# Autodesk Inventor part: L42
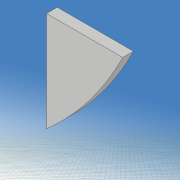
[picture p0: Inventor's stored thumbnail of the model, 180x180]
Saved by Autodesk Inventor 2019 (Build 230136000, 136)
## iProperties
Created: 2021-05
Part Number: L42
Material: 一般
Document SubType Name: Modeling
Designer: kikut
Density: 1 g/cm^3
Appearance: 既定
Mass: 0.00934248 g
Surface Area: 0.426451 cm^2
Volume: 0.00934248 cm^3
Author: kikut
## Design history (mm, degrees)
sketch "スケッチ1"
  geometry: L1 (80, 60)-(-80, 60); L2 (-80, 60)-(-80, -60); L3 (-80, -60)-(80, -60); L4 (80, -60)-(80, 60); L5 (80, 60)-(-80, -60); L6 (-80, 60)-(80, -60); 1 further point
  constraints: 12 end point, 2 midpoint, 2 parallel, 1 horizontal, 1 perpendicular
  dimensions: "d0" = 160 distance of L2.end L3.end; "d1" = 120 distance of L1.end L2.end
extrude "押し出し1" new body sketch "スケッチ1" stored distance "d2" = 0.6; taper "d3" = 0 deg
sketch "スケッチ2"
  geometry: L1 (-140, 0)-(140, 0) reference; L2 (0, -54)-(20, -30); L3 (0, 54)-(20, 30); L4 (0, -3)-(6.514, -3); L5 (6.514, -3)-(16, -6); L6 (16, -6)-(24, -3); L7 (24, -3)-(33.716, -3); L8 (0, 3)-(6.514, 3); L9 (6.514, 3)-(16, 6); L10 (16, 6)-(24, 3); L11 (24, 3)-(33.716, 3); L12 (0, -98)-(0, 98) reference; L13 (-100, -70)-(100, -70); L14 (100, -70)-(100, 70); L15 (100, 70)-(-100, 70); L16 (-100, 70)-(-100, -70); L17 (-100, -70)-(100, 70); L18 (100, -70)-(-100, 70); A1 r 60 centre (54.312, 28.5) between (0, 54) and (0, 3); A2 r 60 centre (54.312, -28.5) between (0, -3) and (0, -54); A3 r 18.111 centre (18, -12) between (20, -30) and (33.716, -3); A4 r 18.111 centre (18, 12) between (33.716, 3) and (20, 30); 1 further point
  constraints: 32 end point, 8 point on circle, 8 symmetric about line, 4 centre point, 3 horizontal, 2 collinear, 2 midpoint, 2 parallel, 1 perpendicular
  dimensions: "d5" = 60 radius of A1; "d6" = 6 distance of L8.start L4.start; "d7" = 108 distance of L3.start L2.start; "d8" = 0 horizontal distance of L3.start L8.start; "d9" = 60 distance of L3.end L2.end; "d10" = 0 horizontal distance of point (0, 0) L3.start; "d11" = 20 horizontal distance of L3.start L3.end; "d12" = 24 distance of A4.centre A3.centre; "d13" = 6 distance of L11.end L7.end; "d14" = 12 distance of L9.end L5.end; "d15" = 16 distance from line of L12 L5.end; "d16" = 24 distance from line of L6.end L12; "d17" = 200 distance of L14.end L15.end; "d18" = 140 distance of L15.end L13.start; "d30" = 18 distance from line of L12 A4.centre
extrude "押し出し2" cut sketch "スケッチ2" stored distance "d19" = 10; taper "d20" = 0 deg
sketch "スケッチ3"
  geometry: L1 (49.705, -17.97)-(33.948, -15.191); L2 (33.948, -15.191)-(34.295, -13.222); L3 (34.295, -13.222)-(50.052, -16); L4 (50.052, -16)-(49.705, -17.97); L5 (49.705, -17.97)-(34.295, -13.222); L6 (33.948, -15.191)-(50.052, -16); L7 (50.052, 16)-(34.295, 13.222); L8 (34.295, 13.222)-(33.948, 15.191); L9 (33.948, 15.191)-(49.705, 17.97); L10 (49.705, 17.97)-(50.052, 16); L11 (50.052, 16)-(33.948, 15.191); L12 (34.295, 13.222)-(49.705, 17.97); L13 (-112, 0)-(112, 0) reference; L14 (0, -84)-(0, 84) reference; 3 further points
  constraints: 24 end point, 4 midpoint, 4 parallel, 2 perpendicular, 2 symmetric about line
  dimensions: "d21" = 2 distance of L3.end L1.start; "d22" = 2 distance of L9.end L7.start; "d23" = 16 distance of L8.end L9.end; "d24" = 42 distance from line of L14 point (42, 15.596); "d26" = 10 deg angle of L7 L13; "d62" = 16 distance from line of L3.end L13
extrude "押し出し3" join sketch "スケッチ3" distance "d27" = 0.6; taper "d28" = 0 deg
fillet "フィレット1" dims "d31" = 2
fillet "フィレット2" dims "d32" = 1
sketch "スケッチ7"
  geometry: L1 (-20, 60)-(80, 60); L2 (80, 60)-(80, -60); L3 (80, -60)-(-20, -60); L4 (-20, -60)-(-20, 60); L5 (0, -82.207)-(0, 85.793) reference; L6 (-40, 0)-(100, 0) reference; L7 (30, -20)-(36, -20); L8 (36, -20)-(36, -30); L9 (36, -30)-(30, -30); L10 (30, -30)-(30, -20); 1 further point
  constraints: 16 end point, 4 parallel, 2 horizontal, 2 perpendicular, 1 other
  dimensions: "d80" = 120 distance of L3.end L1.start; "d81" = 20 distance between parallel lines of L5 L4; "d82" = 100 distance of L1.start L1.end; "d84" = 6 distance of L8.end L9.end; "d85" = 10 distance of L7.end L8.end; "d86" = 50 distance between parallel lines of L4 L10; "d93" = 30 distance between parallel lines of L3 L9
extrude "押し出し5" cut sketch "スケッチ7" stored distance "d87" = 10; taper "d88" = 0 deg
node "ソリッド1"
